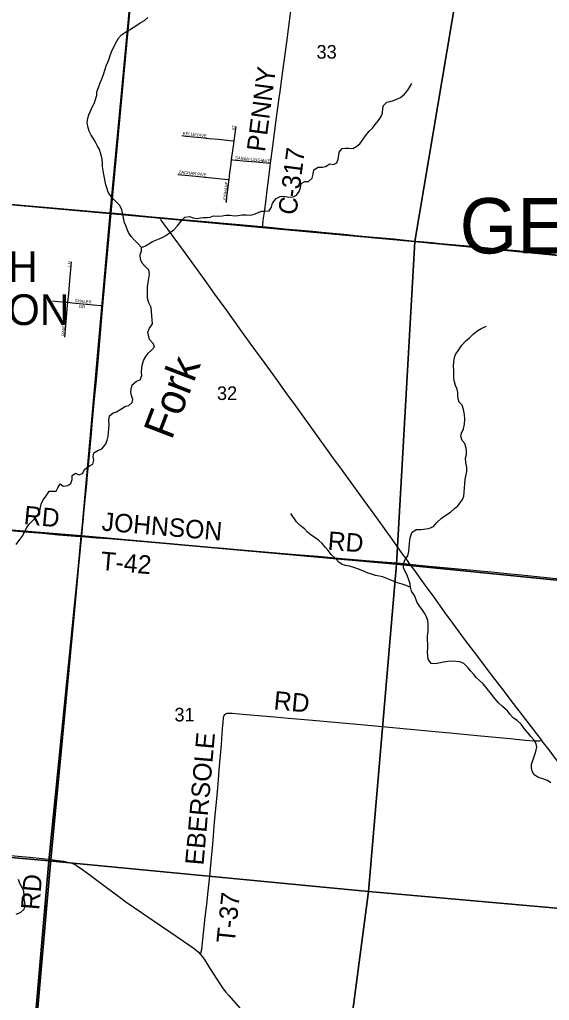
# Model space of a CAD drawing. Extents: x 1410790 to 1770854, y 566777 to 831614.
# Drawn here: x 1567610 to 1576223, y 714986 to 730938 of the extents above; entities that cross this region are included whole.
import ezdxf

# ---------------------------------------------------------------- set-up
doc = ezdxf.new("R2010")
doc.units = 0
for name, color, linetype in [('GM_X_Corporation_Text', 7, 'Continuous'), ('GM_X_County_Road', 7, 'Continuous'), ('GM_X_County_Road_Text', 7, 'Continuous'), ('GM_X_Minor_River', 7, 'Continuous'), ('GM_X_Minor_River_Text', 7, 'Continuous'), ('GM_X_Section', 7, 'Continuous'), ('GM_X_Section_Text', 7, 'Continuous'), ('GM_X_State_Route', 7, 'Continuous'), ('GM_X_Township', 7, 'Continuous'), ('GM_X_Township_Road', 7, 'Continuous'), ('GM_X_Township_Road_Text', 7, 'Continuous'), ('GM_X_Township_Subdivision', 7, 'Continuous'), ('GM_X_Township_Subdivision_Text', 7, 'Continuous'), ('GM_X_Township_Text', 7, 'Continuous')]:
    doc.layers.add(name, color=color, linetype=linetype)

msp = doc.modelspace()

# ---------------------------------------------------------------- linework, layer by layer
at = {"layer": 'GM_X_County_Road'}
for points in [[(1571836, 729706), (1571838, 729725), (1571889, 730099), (1571952, 730571), (1572007, 730993), (1572051, 731335), (1572077, 731530), (1572102, 731709), (1572123, 731871), (1572150, 732083), (1572205, 732506), (1572244, 732798), (1572259, 732913)], [(1571691, 728600), (1571727, 728880), (1571783, 729303), (1571836, 729706)], [(1571559, 727566), (1571562, 727595), (1571572, 727676), (1571590, 727806), (1571611, 727969), (1571635, 728164), (1571655, 728327), (1571686, 728555), (1571691, 728600)], [(1568958, 726287), (1568976, 726476), (1569011, 726885), (1569037, 727178), (1569066, 727472), (1569084, 727668), (1569093, 727773), (1569094, 727788)], [(1571907, 724921), (1571880, 724959), (1571774, 725105), (1571601, 725344), (1571361, 725676), (1571208, 725889), (1570969, 726222), (1570786, 726474), (1570614, 726713), (1570257, 727204), (1570124, 727388), (1570037, 727510), (1569957, 727615), (1569910, 727677), (1569905, 727686), (1569901, 727696), (1569898, 727715)], [(1568824, 724771), (1568852, 725071), (1568879, 725382), (1568902, 725659), (1568952, 726215), (1568958, 726287)], [(1573956, 722083), (1573914, 722140), (1573819, 722273), (1573666, 722488), (1573416, 722832), (1573167, 723178), (1572857, 723606), (1572705, 723815), (1572359, 724294), (1572207, 724507), (1572072, 724693), (1571957, 724853), (1571907, 724921)], [(1568613, 722532), (1568636, 722769), (1568655, 722965), (1568695, 723389), (1568710, 723536), (1568735, 723797), (1568751, 723977), (1568772, 724206), (1568785, 724353), (1568824, 724771)], [(1568120, 717279), (1568135, 717430), (1568172, 717839), (1568188, 718018), (1568223, 718377), (1568254, 718704), (1568275, 718932), (1568294, 719145), (1568317, 719390), (1568334, 719552), (1568354, 719765), (1568410, 720336), (1568452, 720777), (1568471, 720989), (1568504, 721332), (1568524, 721544), (1568545, 721773), (1568581, 722181), (1568605, 722443), (1568613, 722532)], [(1576098, 719216), (1576019, 719319), (1575930, 719437), (1575641, 719815), (1575453, 720061), (1575344, 720204), (1575234, 720348), (1575027, 720623), (1574878, 720818), (1574799, 720923), (1574653, 721121), (1574530, 721291), (1574414, 721453), (1574348, 721544), (1574193, 721756), (1574019, 721998), (1573956, 722083)], [(1578334, 716312), (1578311, 716346), (1578271, 716399), (1578137, 716565), (1578045, 716680), (1577975, 716771), (1577845, 716940), (1577755, 717057), (1577575, 717291), (1577505, 717381), (1577385, 717537), (1577326, 717616), (1577236, 717733), (1577177, 717811), (1576997, 718045), (1576937, 718123), (1576787, 718318), (1576697, 718435), (1576557, 718617), (1576448, 718760), (1576308, 718942), (1576218, 719059), (1576108, 719202), (1576098, 719216)], [(1566283, 717408), (1566529, 717399), (1566693, 717394), (1566857, 717389), (1567070, 717380), (1567184, 717372), (1567347, 717357), (1567527, 717339), (1567772, 717315), (1567984, 717294), (1568120, 717279)], [(1567848, 714189), (1567864, 714393), (1567879, 714589), (1567889, 714703), (1567916, 715014), (1567938, 715259), (1567954, 715438), (1567972, 715634), (1567991, 715846), (1568008, 716043), (1568019, 716173), (1568035, 716353), (1568048, 716500), (1568061, 716647), (1568078, 716826), (1568092, 716973), (1568103, 717087), (1568117, 717251), (1568120, 717279)], [(1568120, 717279), (1568233, 717263), (1568330, 717248), (1568394, 717235), (1568441, 717222), (1568472, 717211), (1568501, 717199), (1568530, 717183), (1568558, 717166), (1568598, 717138), (1568733, 717038), (1569019, 716825), (1569243, 716659), (1569336, 716591), (1569593, 716415), (1569782, 716286), (1570067, 716092), (1570379, 715880), (1570432, 715842), (1570483, 715801), (1570519, 715768), (1570548, 715737)], [(1570548, 715737), (1570553, 715732), (1570583, 715694), (1570620, 715640), (1570699, 715516), (1570876, 715239), (1570922, 715171), (1570961, 715119), (1571004, 715068), (1571199, 714847)]]:
    msp.add_lwpolyline(points, dxfattribs=at)
at = {"layer": 'GM_X_Minor_River'}
for points in [[(1569572, 725079), (1569597, 725147), (1569592, 725201), (1569599, 725273), (1569609, 725333), (1569626, 725391), (1569663, 725459), (1569702, 725513), (1569753, 725560), (1569805, 725614), (1569782, 725672), (1569719, 725735), (1569706, 725803), (1569696, 725854), (1569723, 725919), (1569770, 725991), (1569763, 726057), (1569758, 726127), (1569754, 726184), (1569749, 726258), (1569710, 726330), (1569691, 726405), (1569688, 726481), (1569688, 726535), (1569687, 726593), (1569698, 726661), (1569711, 726725), (1569720, 726793), (1569711, 726866), (1569657, 726916), (1569604, 726977), (1569574, 727040), (1569571, 727110), (1569592, 727178), (1569593, 727234), (1569537, 727293), (1569470, 727358), (1569426, 727408), (1569379, 727475), (1569360, 727529), (1569330, 727598), (1569309, 727648), (1569298, 727717), (1569286, 727771), (1569271, 727845), (1569240, 727916), (1569193, 727966), (1569125, 728031), (1569082, 728082), (1569052, 728132), (1569031, 728183), (1569012, 728249), (1569002, 728303), (1568989, 728362), (1568977, 728418), (1568966, 728484), (1568959, 728551), (1568956, 728603), (1568954, 728661), (1568943, 728719), (1568926, 728773), (1568906, 728826), (1568873, 728888), (1568836, 728955), (1568808, 729007), (1568775, 729058), (1568743, 729122), (1568720, 729197), (1568709, 729267), (1568720, 729335), (1568737, 729391), (1568799, 729535), (1568825, 729586), (1568846, 729638), (1568865, 729708), (1568866, 729766), (1568891, 729834), (1568922, 729908), (1568946, 729974), (1568973, 730044), (1569000, 730132), (1569019, 730184), (1569046, 730247), (1569065, 730301), (1569090, 730369), (1569115, 730443), (1569150, 730511), (1569172, 730563), (1569217, 730636), (1569266, 730688), (1569333, 730733), (1569395, 730770), (1569458, 730810), (1569515, 730845), (1569569, 730885), (1569638, 730926), (1569693, 730971)], [(1569593, 727230), (1569655, 727261), (1569710, 727289), (1569772, 727330), (1569825, 727353), (1569881, 727373), (1569936, 727398), (1569988, 727428), (1570049, 727469), (1570118, 727520), (1570177, 727584), (1570234, 727659), (1570297, 727725), (1570375, 727736), (1570427, 727713), (1570489, 727704), (1570549, 727714), (1570601, 727721), (1570652, 727720), (1570710, 727724), (1570760, 727749), (1570830, 727742), (1570905, 727746), (1570963, 727759), (1571031, 727758), (1571103, 727747), (1571165, 727752), (1571230, 727762), (1571298, 727763), (1571366, 727760), (1571430, 727773), (1571499, 727805), (1571549, 727822), (1571599, 727822), (1571668, 727827), (1571707, 727888), (1571723, 727954), (1571780, 728028), (1571845, 728063), (1571907, 728066), (1571987, 728048), (1572058, 728053), (1572110, 728080), (1572157, 728142), (1572178, 728204), (1572189, 728270), (1572247, 728303), (1572309, 728304), (1572364, 728360), (1572383, 728426), (1572396, 728494), (1572463, 728539), (1572535, 728536), (1572585, 728550), (1572656, 728591), (1572714, 728582), (1572768, 728606), (1572789, 728666), (1572798, 728732), (1572807, 728782), (1572855, 728841), (1572906, 728849), (1572962, 728848), (1573030, 728839), (1573093, 728882), (1573143, 728920), (1573196, 728994), (1573233, 729045), (1573292, 729123), (1573349, 729172), (1573392, 729230), (1573443, 729295), (1573490, 729363), (1573508, 729421), (1573515, 729491), (1573526, 729543), (1573579, 729596), (1573633, 729608), (1573689, 729621), (1573752, 729647), (1573802, 729670), (1573869, 729725), (1573922, 729793), (1573953, 729845), (1573986, 729900)], [(1574155, 721341), (1574118, 721393), (1574071, 721460), (1574028, 721573), (1573983, 721641), (1573967, 721708), (1573958, 721760), (1573942, 721810), (1573917, 721883), (1573851, 722020), (1573850, 722088), (1573879, 722156), (1573923, 722219), (1573938, 722289), (1573943, 722362), (1573948, 722414), (1573955, 722476), (1573963, 722528), (1573986, 722596), (1574059, 722645), (1574139, 722646), (1574214, 722653), (1574264, 722663), (1574340, 722696), (1574391, 722761), (1574468, 722827), (1574541, 722876), (1574618, 722925), (1574679, 722984), (1574734, 723028), (1574772, 723080), (1574811, 723133), (1574832, 723189), (1574839, 723247), (1574843, 723321), (1574846, 723389), (1574855, 723457), (1574864, 723510), (1574879, 723586), (1574882, 723652), (1574863, 723734), (1574861, 723804), (1574878, 723864), (1574875, 723918), (1574872, 723970), (1574846, 724043), (1574807, 724094), (1574782, 724162), (1574792, 724212), (1574829, 724284), (1574844, 724358), (1574847, 724440), (1574844, 724514), (1574829, 724596), (1574806, 724667), (1574756, 724718), (1574739, 724768), (1574736, 724820), (1574734, 724874), (1574725, 724926), (1574699, 724987), (1574678, 725049), (1574671, 725099), (1574672, 725162), (1574668, 725232), (1574667, 725300), (1574670, 725370), (1574681, 725440), (1574698, 725492), (1574743, 725564), (1574800, 725641), (1574863, 725715), (1574922, 725762), (1574987, 725825), (1575059, 725881), (1575126, 725922), (1575199, 725951)], [(1567556, 722399), (1567611, 722483), (1567660, 722548), (1567691, 722606), (1567728, 722676), (1567765, 722734), (1567844, 722813), (1567903, 722880), (1567938, 722950), (1567959, 723054), (1567994, 723126), (1568049, 723199), (1568092, 723267), (1568152, 723266), (1568202, 723266), (1568231, 723325), (1568268, 723387), (1568320, 723352), (1568394, 723359), (1568445, 723393), (1568465, 723459), (1568462, 723523), (1568517, 723560), (1568571, 723532), (1568633, 723555), (1568670, 723625), (1568745, 723680), (1568799, 723707), (1568816, 723773), (1568803, 723824), (1568814, 723894), (1568880, 723931), (1568949, 723954), (1569008, 724026), (1569033, 724097), (1569052, 724161), (1569056, 724217), (1569063, 724282), (1569064, 724350), (1569063, 724420), (1569072, 724492), (1569131, 724543), (1569187, 724559), (1569256, 724602), (1569334, 724649), (1569387, 724659), (1569441, 724708), (1569448, 724758), (1569431, 724824), (1569419, 724879), (1569422, 724929), (1569441, 724997), (1569510, 725058), (1569572, 725079)], [(1573968, 721702), (1573893, 721733), (1573829, 721756), (1573756, 721776), (1573700, 721797), (1573634, 721824), (1573578, 721849), (1573518, 721875), (1573456, 721886), (1573398, 721899), (1573330, 721916), (1573276, 721936), (1573190, 721973), (1573119, 722002), (1573043, 722025), (1572975, 722050), (1572907, 722061), (1572853, 722076), (1572799, 722116), (1572746, 722171), (1572678, 722238), (1572629, 722301), (1572583, 722353), (1572530, 722418), (1572472, 722471), (1572401, 722522), (1572345, 722559), (1572288, 722602), (1572240, 722654), (1572171, 722709), (1572111, 722768), (1572020, 722905)], [(1576245, 718524), (1576191, 718562), (1576119, 718591), (1576045, 718612), (1575977, 718655), (1575946, 718716), (1575935, 718770), (1575935, 718826), (1575952, 718886), (1575975, 718952), (1576004, 719032), (1576017, 719104), (1576008, 719158), (1575976, 719220), (1575919, 719279), (1575876, 719332), (1575816, 719409), (1575767, 719478), (1575700, 719536), (1575642, 719577), (1575588, 719636), (1575545, 719693), (1575462, 719764), (1575394, 719827), (1575339, 719894), (1575280, 719964), (1575210, 720051), (1575149, 720134), (1575092, 720183), (1575032, 720236), (1574993, 720286), (1574939, 720345), (1574902, 720396), (1574832, 720463), (1574767, 720494), (1574701, 720500), (1574628, 720503), (1574566, 720498), (1574500, 720489), (1574427, 720472), (1574371, 720462), (1574301, 720467), (1574254, 720536), (1574248, 720586), (1574243, 720662), (1574248, 720714), (1574247, 720784), (1574243, 720841), (1574244, 720915), (1574251, 720987), (1574254, 721039), (1574251, 721097), (1574247, 721163), (1574224, 721222), (1574191, 721286), (1574155, 721341)], [(1567554, 716387), (1567626, 716414), (1567683, 716469), (1567700, 716535), (1567697, 716585), (1567685, 716638), (1567684, 716690), (1567677, 716760), (1567648, 716829), (1567616, 716887), (1567589, 716952)]]:
    msp.add_lwpolyline(points, dxfattribs=at)
at = {"layer": 'GM_X_Section'}
for points in [[(1569584, 733136), (1569081, 727784), (1563860, 728250), (1564358, 733651)], [(1569584, 733136), (1574933, 732667), (1574037, 727327), (1569081, 727784)], [(1579852, 732153), (1579378, 726811), (1574037, 727327), (1574933, 732667)], [(1563860, 728250), (1569081, 727784), (1568614, 722540), (1563333, 722968)], [(1569081, 727784), (1574037, 727327), (1573738, 722079), (1568614, 722540)], [(1574037, 727327), (1579378, 726811), (1578901, 721568), (1573738, 722079)], [(1563333, 722968), (1568614, 722540), (1568083, 717254), (1562844, 717721)], [(1568614, 722540), (1573738, 722079), (1573282, 716756), (1568083, 717254)], [(1573738, 722079), (1578901, 721568), (1578419, 716300), (1573282, 716756)], [(1562844, 717721), (1568083, 717254), (1567631, 711959), (1562327, 712403)], [(1568083, 717254), (1573282, 716756), (1572586, 711496), (1567631, 711959)], [(1573282, 716756), (1578419, 716300), (1577924, 711041), (1572586, 711496)]]:
    msp.add_lwpolyline(points, close=True, dxfattribs=at)
at = {"layer": 'GM_X_State_Route'}
msp.add_lwpolyline([(1576323, 727115), (1576107, 727135), (1575849, 727159), (1575686, 727176), (1575506, 727192), (1575276, 727214), (1575018, 727240), (1574642, 727275), (1574446, 727293), (1574316, 727306), (1574185, 727319), (1573989, 727337), (1573695, 727365), (1573505, 727383), (1573304, 727401), (1573126, 727418), (1572882, 727443), (1572523, 727475), (1572376, 727490), (1572180, 727507), (1571919, 727532), (1571723, 727550), (1571559, 727566), (1571543, 727567), (1571184, 727599), (1570872, 727628), (1570635, 727650), (1570319, 727678), (1570188, 727688), (1569898, 727715), (1569763, 727727), (1569338, 727766), (1569094, 727788), (1569012, 727795), (1568456, 727843), (1568211, 727865), (1567770, 727905), (1567231, 727953)], dxfattribs=at)
at = {"layer": 'GM_X_Township'}
for points in [[(1570609, 743817), (1570350, 741134), (1569590, 733145), (1569094, 727788), (1568958, 726287), (1568879, 725382), (1568852, 725071), (1568824, 724771), (1568785, 724353), (1568772, 724206), (1568751, 723977), (1568735, 723797), (1568710, 723536), (1568695, 723389), (1568655, 722965), (1568636, 722769), (1568613, 722532), (1568504, 721332), (1568294, 719145), (1568120, 717279), (1567848, 714189)], [(1567848, 714189), (1568120, 717279), (1568294, 719145), (1568504, 721332), (1568613, 722532), (1568636, 722769), (1568655, 722965), (1568695, 723389), (1568710, 723536), (1568735, 723797), (1568751, 723977), (1568772, 724206), (1568785, 724353), (1568824, 724771), (1568852, 725071), (1568879, 725382), (1568958, 726287), (1569094, 727788), (1569590, 733145), (1570350, 741134), (1570609, 743817)]]:
    msp.add_lwpolyline(points, dxfattribs=at)
at = {"layer": 'GM_X_Township_Road'}
for points in [[(1564826, 722854), (1564989, 722836), (1565153, 722822), (1565431, 722796), (1565594, 722782), (1565774, 722767), (1565921, 722755), (1566019, 722747), (1566183, 722733), (1566379, 722719), (1566526, 722707), (1566690, 722692), (1566771, 722684), (1566869, 722677), (1567115, 722655), (1567262, 722643), (1567458, 722626), (1567769, 722601), (1567981, 722584), (1568243, 722560), (1568521, 722538), (1568613, 722532)], [(1568613, 722532), (1568648, 722529), (1568681, 722527), (1568861, 722511), (1569058, 722496), (1570007, 722417), (1570187, 722402), (1570531, 722373), (1570711, 722357), (1570923, 722339), (1571152, 722319), (1572102, 722239), (1572249, 722226), (1572462, 722209), (1572789, 722180), (1573182, 722147), (1573444, 722126), (1573804, 722096), (1573956, 722083)], [(1573956, 722083), (1574004, 722077), (1574208, 722056), (1574747, 722004), (1575335, 721948), (1575531, 721929), (1575711, 721912), (1575923, 721890), (1576282, 721853), (1576559, 721822), (1576739, 721803), (1577180, 721757), (1577506, 721720), (1577816, 721687), (1577995, 721667), (1578436, 721617), (1578664, 721594), (1579236, 721535), (1579612, 721500), (1579906, 721473), (1580494, 721417), (1580804, 721390), (1581577, 721318)], [(1570548, 715737), (1570554, 715752), (1570559, 715765), (1570563, 715782), (1570570, 715819), (1570629, 716340), (1570652, 716552), (1570675, 716763), (1570701, 717008), (1570730, 717302), (1570745, 717465), (1570762, 717661), (1570781, 717889), (1570815, 718265), (1570830, 718444), (1570841, 718575), (1570855, 718738), (1570890, 719146), (1570911, 719408), (1570921, 719506), (1570927, 719588), (1570930, 719604), (1570935, 719619), (1570944, 719633), (1570956, 719643), (1570967, 719649), (1570970, 719651), (1570986, 719656), (1571002, 719658), (1571035, 719660), (1571068, 719659), (1571296, 719636), (1571623, 719607), (1571753, 719595), (1571982, 719575), (1572373, 719541), (1572553, 719525), (1573157, 719473), (1573908, 719401), (1574365, 719359), (1574609, 719335), (1575050, 719295), (1575587, 719245), (1575837, 719220), (1575971, 719209), (1575973, 719208)], [(1575973, 719208), (1576020, 719205), (1576040, 719205), (1576062, 719209), (1576088, 719214), (1576098, 719216)]]:
    msp.add_lwpolyline(points, dxfattribs=at)
at = {"layer": 'GM_X_Township_Subdivision'}
for points in [[(1571097, 728964), (1571114, 729083), (1571130, 729202)], [(1570249, 729051), (1570314, 729044), (1570560, 729018), (1570691, 729006), (1570838, 728991), (1571083, 728966), (1571097, 728964)], [(1571057, 728661), (1571091, 728918), (1571097, 728964)], [(1571016, 728339), (1571030, 728445), (1571048, 728592), (1571057, 728661)], [(1571057, 728661), (1571079, 728659), (1571243, 728643), (1571454, 728623), (1571677, 728602), (1571691, 728600)], [(1570182, 728421), (1570299, 728410), (1570480, 728392), (1570628, 728378), (1571003, 728340), (1571016, 728339)], [(1570971, 727966), (1570981, 728053), (1571000, 728216), (1571016, 728339)], [(1568395, 726340), (1568409, 726481), (1568427, 726695), (1568444, 726876), (1568450, 726942), (1568455, 726997)], [(1568146, 726363), (1568236, 726355), (1568367, 726343), (1568395, 726340)], [(1568345, 725774), (1568361, 725955), (1568385, 726235), (1568395, 726340)], [(1568395, 726340), (1568466, 726332), (1568811, 726301), (1568927, 726290), (1568958, 726287)]]:
    msp.add_lwpolyline(points, dxfattribs=at)

# ---------------------------------------------------------------- texts
at = {"layer": 'GM_X_Corporation_Text'}
for s, p in [('NORTH', (1565529, 726669)), ('HAMPTON', (1565078, 725970))]:
    msp.add_text(s, height=500, rotation=0, dxfattribs=at).set_placement(p)
at = {"layer": 'GM_X_County_Road_Text'}
for s, rotation, p in [('PENNY', 82.5952, (1571599, 728778)), ('C-317', 82.5349, (1572109, 727750)), ('RD', 85.0773, (1567928, 716449))]:
    msp.add_text(s, height=300, rotation=rotation, dxfattribs=at).set_placement(p)
at = {"layer": 'GM_X_Minor_River_Text'}
msp.add_text('Fork', height=499.8, rotation=69.0011, dxfattribs=at).set_placement((1570080, 724088))
at = {"layer": 'GM_X_Section_Text'}
for s, p in [('33', (1572437, 730303)), ('32', (1570818, 724751)), ('31', (1570127, 719523))]:
    msp.add_text(s, height=221, rotation=0, dxfattribs=at).set_placement(p)
at = {"layer": 'GM_X_Township_Road_Text'}
for s, rotation, p in [('RD', 354.5877, (1567669, 722733)), ('JOHNSON', 355.2107, (1568936, 722628)), ('RD', 355.5636, (1572612, 722316)), ('T-42', 355.0597, (1568917, 721988)), ('RD', 354.5825, (1571732, 719720)), ('EBERSOLE', 85.0128, (1570599, 717176)), ('T-37', 84.0115, (1571107, 715905))]:
    msp.add_text(s, height=300, rotation=rotation, dxfattribs=at).set_placement(p)
at = {"layer": 'GM_X_Township_Subdivision_Text'}
for s, rotation, p in [('ST', 82.8666, (1571112, 729134)), ('KELLEY', 354.7089, (1570260, 729063)), ('AVE', 354.0977, (1570515, 729036)), ('SARAH-LEIGH', 354.4734, (1571109, 728667)), ('AVE', 356.0569, (1571549, 728623)), ('ZACHARY', 354.8821, (1570194, 728434)), ('A', 353.737, (1570511, 728403)), ('V', 353.7153, (1570555, 728398)), ('E', 354.6936, (1570599, 728393)), ('JOSHANE', 83.5584, (1570967, 727977)), ('L', 88.0872, (1568441, 726919)), ('N', 85.8879, (1568443, 726954)), ('SHALER', 354.7085, (1568504, 726344)), ('DR', 353.9832, (1568575, 726250)), ('RANDEE', 84.8967, (1568340, 725790))]:
    msp.add_text(s, height=50, rotation=rotation, dxfattribs=at).set_placement(p)
at = {"layer": 'GM_X_Township_Text'}
msp.add_text('GERMAN', height=900, rotation=0, dxfattribs=at).set_placement((1574765, 727135))

doc.saveas('drawing.dxf')
